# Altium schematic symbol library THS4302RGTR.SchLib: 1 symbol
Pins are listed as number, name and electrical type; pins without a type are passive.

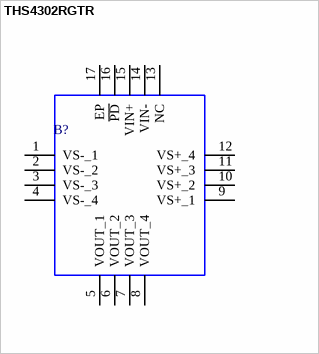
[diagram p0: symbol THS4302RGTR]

## THS4302RGTR
designator B?
2.4GHz, Wideband Fixed Gain Amplifier; Manufacturer_Name: Texas Instruments; Geometry.Height: 1mm
footprint QFN50P300X300X100-17N-D
pins: 1 VS-_1, 2 VS-_2, 3 VS-_3, 4 VS-_4, 5 VOUT_1, 6 VOUT_2, 7 VOUT_3, 8 VOUT_4, 9 VS+_1, 10 VS+_2, 11 VS+_3, 12 VS+_4, 13 NC, 14 VIN-, 15 VIN+, 16 ~{PD}, 17 EP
